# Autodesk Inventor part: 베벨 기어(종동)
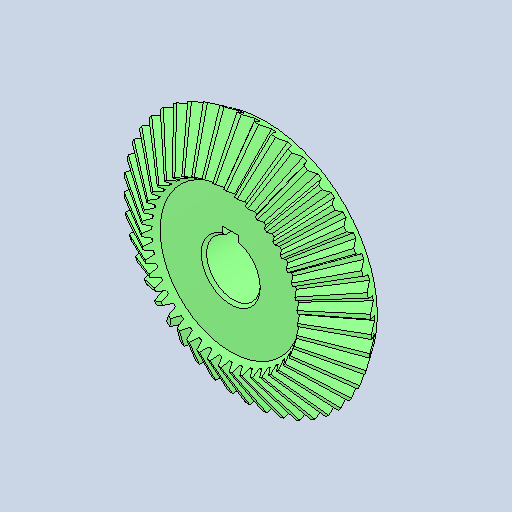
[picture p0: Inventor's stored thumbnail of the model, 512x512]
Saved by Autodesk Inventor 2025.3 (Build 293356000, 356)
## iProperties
Created: 2026-01
Part Number: 베벨 기어(종동)
Material: 강철, 합금
Document SubType Name: Modeling
Designer: pc6
Density: 7.73 g/cm^3
Appearance: 기본값
Author: jhkim
Sending System: Autodesk Inventor 2026
Preprocessor: ST-DEVELOPER v20.1
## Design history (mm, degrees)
feature "Solid1"
node "솔리드1"
